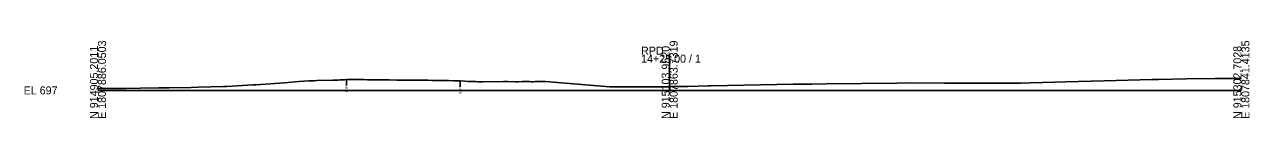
# Model space of a CAD drawing. Extents: x -26 to 403, y -10 to 8517.
# Drawn here: x -25.7 to 402.8, y 8490.3 to 8517.3 of the extents above; entities that cross this region are included whole.
import ezdxf

# ---------------------------------------------------------------- set-up
doc = ezdxf.new("R2010")
doc.units = 0
for name, color, linetype in [('Exist Cross Section Cell', 7, 'Continuous'), ('Exist XS Center Line Elevation Label', 7, 'Continuous'), ('Exist XS Ground Line', 7, 'Continuous'), ('Old_Level_10', 7, 'Continuous')]:
    doc.layers.add(name, color=color, linetype=linetype)

msp = doc.modelspace()

# ---------------------------------------------------------------- linework, layer by layer
at = {"layer": 'Exist Cross Section Cell'}
for p, q in [((200, 8500), (200, 8512.51)), ((0, 8500), (200, 8500)), ((200, 8500), (400, 8500))]:
    msp.add_line(p, q, dxfattribs=at)
at = {"layer": 'Exist XS Ground Line'}
msp.add_lwpolyline([(0, 8500.62), (4.83, 8500.62), (9.92, 8500.7), (14.89, 8500.79), (21.25, 8500.86), (24.95, 8500.88), (32.59, 8501.07), (35.02, 8501.13), (43.92, 8501.4), (45.08, 8501.42), (54.22, 8501.9), (55.26, 8501.95), (65.21, 8502.67), (70.24, 8503.06), (73.72, 8503.31), (74.22, 8503.36), (75.2, 8503.38), (75.61, 8503.4), (76.57, 8503.42), (82.2, 8503.59), (83.88, 8503.64), (84.64, 8503.68), (86.21, 8503.74), (86.99, 8503.78), (88.03, 8503.78), (89.31, 8503.78), (90.03, 8503.77), (91.83, 8503.77), (92.88, 8503.76), (94.34, 8503.75), (95.52, 8503.74), (96.86, 8503.73), (98.54, 8503.72), (99.37, 8503.7), (101.37, 8503.68), (101.89, 8503.68), (104.56, 8503.64), (105.97, 8503.62), (107.04, 8503.61), (109.43, 8503.61), (111.34, 8503.59), (111.95, 8503.58), (113.61, 8503.56), (114.47, 8503.54), (115.54, 8503.53), (116.99, 8503.51), (118.38, 8503.49), (119.5, 8503.47), (121.22, 8503.44), (122.02, 8503.43), (122.66, 8503.41), (124.53, 8503.38), (125.17, 8503.37), (126.08, 8503.36), (126.76, 8503.35), (128.36, 8503.25), (129.57, 8503.16), (131.7, 8503.08), (132.07, 8503.07), (132.73, 8503.04), (134.62, 8503.05), (141.9, 8503.06), (143.31, 8503.06), (146.06, 8503.05), (147, 8503.05), (148.41, 8503.06), (148.9, 8503.07), (149.95, 8503.06), (150.64, 8503.06), (151.03, 8503.06), (151.55, 8503.04), (151.94, 8503.04), (152.35, 8503.03), (152.94, 8503.06), (153.29, 8503.06), (153.62, 8503.06), (153.94, 8503.07), (156.6, 8503.08), (178.91, 8501.24), (199.08, 8501.23), (200, 8501.28), (200.43, 8501.31), (201.16, 8501.32), (206.37, 8501.38), (213.42, 8501.55), (214.15, 8501.55), (214.53, 8501.55), (243.17, 8502.17), (244.5, 8502.19), (249.65, 8502.24), (254.8, 8502.31), (279.58, 8502.56), (282.71, 8502.61), (296.12, 8502.59), (322.82, 8502.55), (326.09, 8502.66), (334.75, 8502.92), (338.46, 8503.01), (351.99, 8503.4), (368.82, 8503.83), (370.95, 8503.87), (380.74, 8504.05), (390.69, 8504.11), (400, 8504.17)], dxfattribs=at)
at = {"layer": 'Old_Level_10'}
for p, q in [((86.99, 8503.78), (86.99, 8501.73)), ((126.76, 8503.35), (126.76, 8501.3))]:
    msp.add_line(p, q, dxfattribs=at)

# ---------------------------------------------------------------- texts
at = {"layer": 'Exist Cross Section Cell'}
for s, p in [('N 914905.2011', (0, 8490)), ('E 1807886.0503', (2.8, 8490)), ('N 915103.9520', (200, 8490)), ('E 1807863.7319', (202.8, 8490)), ('N 915302.7028', (400, 8490)), ('E 1807841.4135', (402.8, 8490))]:
    msp.add_text(s, height=2.8, rotation=90, dxfattribs=at).set_placement(p)
for s, p in [('RPD', (190, 8512.51)), ('14+25.00 / 1', (190, 8509.71)), ('EL 697', (-26, 8498.6))]:
    msp.add_text(s, height=2.8, dxfattribs=at).set_placement(p)
at = {"layer": 'Exist XS Center Line Elevation Label'}
msp.add_text('698.28', height=1, dxfattribs=at).set_placement((197.86, 8499.28))
at = {"layer": 'Old_Level_10'}
for p in [(87.38, 8499.33), (127.15, 8498.9)]:
    msp.add_text('EOP', height=0.787, rotation=90, dxfattribs=at).set_placement(p)

doc.saveas('drawing.dxf')
